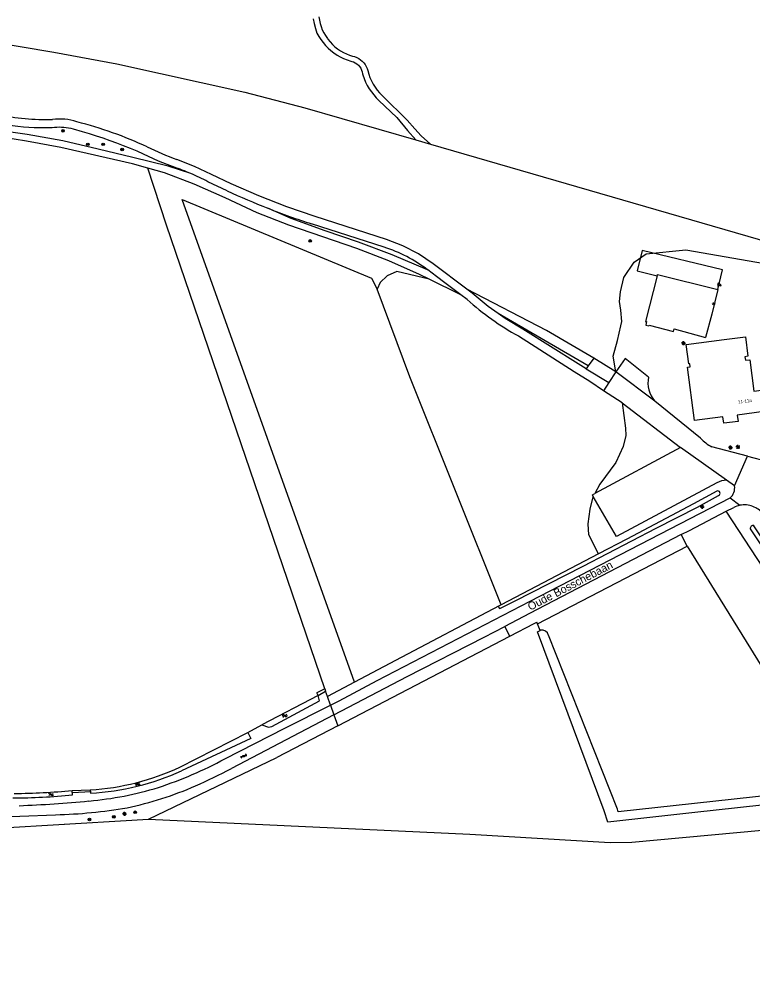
# Model space of a CAD drawing. Extents: x 137000 to 140001, y 403500 to 406000.
# Drawn here: x 138245 to 138474.3, y 405497.8 to 405796.6 of the extents above; entities that cross this region are included whole.
import ezdxf

# ---------------------------------------------------------------- set-up
doc = ezdxf.new("R2010")
doc.units = 0
for name, color, linetype in [('gg-afsc-draadraster', 7, 'Continuous'), ('gg-afsc-erfafscheiding', 7, 'Continuous'), ('gg-afsc-lijn draadraster', 7, 'Continuous'), ('gg-anno-huisnummerreeks BGT', 7, 'Continuous'), ('gg-anno-openbare ruimte label', 7, 'Continuous'), ('gg-bbg-bijgebouw', 7, 'Continuous'), ('gg-bbg-hoofdgebouw', 7, 'Continuous'), ('gg-bbg-luifel en loopbrug', 7, 'Continuous'), ('gg-knt-bronhoudergrens', 7, 'Continuous'), ('gg-knt-onverhard', 7, 'Continuous'), ('gg-knt-verharding', 7, 'Continuous'), ('gg-knt-verharding nz', 7, 'Continuous'), ('gg-kntw-bovenkant insteek waterloop', 7, 'Continuous'), ('gg-kwrk-duiker nz buis', 7, 'Continuous'), ('gt-grn-groengrens', 7, 'Continuous'), ('gt-grn-groengrens NZ', 7, 'Continuous'), ('gt-grn-weggrens', 7, 'Continuous'), ('gt-symb-boom', 7, 'Continuous'), ('gt-symb-camera', 7, 'Continuous'), ('gt-symb-gesloten verharding', 7, 'Continuous'), ('gt-symb-lichtmast', 7, 'Continuous'), ('gt-symb-lichtpunt', 7, 'Continuous'), ('gt-symb-watersymbool', 7, 'Continuous'), ('gx-grn-maaiveld', 7, 'Continuous')]:
    doc.layers.add(name, color=color, linetype=linetype)

# ---------------------------------------------------------------- blocks, each defined once
blk = doc.blocks.new('gt0-BOOM')
at = {"layer": 'gt-symb-boom'}
for radius in [0.4, 0.2]:
    blk.add_circle((0, 0), radius, dxfattribs=at)
blk = doc.blocks.new('gt0-WA')
at = {"layer": 'gt-symb-watersymbool'}
for centre, start, end in [((-0.32, 0.02), 28.0725, 151.9275), ((0.43, 0.42), 208.0725, 331.9275), ((-0.32, -0.43), 28.0725, 151.9275), ((0.43, -0.03), 208.0725, 331.9275)]:
    blk.add_arc(centre, 0.425, start, end, dxfattribs=at)
blk = doc.blocks.new('gt0-GESVH1')
at = {"layer": 'gt-symb-gesloten verharding'}
for p, q in [((-0.99, -0.26), (0.01, 0.24)), ((0.01, -0.26), (-0.99, 0.24)), ((0.01, 0.24), (1.01, -0.26)), ((1.01, 0.24), (0.01, -0.26))]:
    blk.add_line(p, q, dxfattribs=at)
blk = doc.blocks.new('gt0-LMAST')
at = {"layer": 'gt-symb-lichtmast'}
for p, q in [((-0.18, 0.17), (-0.45, 0.44)), ((-0.01, 0.25), (-0.01, 0.62)), ((0.17, 0.17), (0.44, 0.44)), ((-0.26, 0), (-0.63, 0)), ((-0.18, -0.18), (-0.45, -0.45)), ((-0.01, -0.25), (-0.01, -0.63)), ((0.44, -0.45), (0.17, -0.18)), ((0.24, 0), (0.62, 0))]:
    blk.add_line(p, q, dxfattribs=at)
blk.add_circle((-0.01, 0), 0.25, dxfattribs=at)
blk = doc.blocks.new('gt0-LPUNT')
at = {"layer": 'gt-symb-lichtpunt'}
for p, q in [((0, 0), (-0.25, 0)), ((0, 0), (0.25, 0)), ((-0.18, -0.18), (-0.44, -0.44)), ((0, -0.25), (0, -0.62)), ((0.44, -0.44), (0.18, -0.18))]:
    blk.add_line(p, q, dxfattribs=at)
blk.add_arc((0, 0), 0.25, 180, 0, dxfattribs=at)
blk = doc.blocks.new('gt0-CAMERA')
at = {"layer": 'gt-symb-camera'}
for points in [[(0.07, 0.48), (0.75, 0.16), (0.92, 0.51), (-0.12, 1), (-0.28, 0.65), (-0.07, 0.55)], [(0.07, 0.48), (0.07, 0), (-0.07, 0), (-0.07, 0.55)]]:
    blk.add_lwpolyline(points, dxfattribs=at)

msp = doc.modelspace()

# ---------------------------------------------------------------- linework, layer by layer
at = {"layer": 'gg-afsc-draadraster'}
msp.add_lwpolyline([(138285.47, 405546.77), (138385.85, 405542.03), (138429.7, 405539.4), (138436.46, 405539.56), (138519.15, 405547.11), (138520.63, 405545.63), (138532.33, 405527.32), (138568.1, 405472.11), (138619.55, 405394.28), (138620.49, 405392.37), (138614.17, 405385.79)], dxfattribs=at)
at = {"layer": 'gg-afsc-erfafscheiding'}
msp.add_lwpolyline([(138431.55, 405686.42), (138430.73, 405691.32), (138432.04, 405696.3), (138433.12, 405700.81), (138433.36, 405702.15), (138433.12, 405705.77), (138432.66, 405708.47), (138432.93, 405711.45), (138433.97, 405715.93), (138437.22, 405720.74), (138440.96, 405723.28), (138453.34, 405724.56), (138477.96, 405720.34)], dxfattribs=at)
at = {"layer": 'gg-afsc-lijn draadraster'}
for points in [[(138226.23, 405542.25), (138232.8, 405543.63), (138285.47, 405546.77)], [(138285.47, 405546.77), (138385.85, 405542.03), (138429.7, 405539.4), (138436.46, 405539.56), (138519.15, 405547.11), (138520.63, 405545.63), (138532.33, 405527.32), (138568.1, 405472.11), (138619.55, 405394.28), (138620.49, 405392.37), (138614.17, 405385.79)]]:
    msp.add_lwpolyline(points, dxfattribs=at)
at = {"layer": 'gg-bbg-bijgebouw'}
for points in [[(138444.42, 405716.42), (138440.83, 405702.23), (138441.12, 405702.15), (138440.87, 405701.09), (138441.86, 405700.85), (138441.91, 405701.07), (138449.54, 405699.07), (138449.76, 405699.89), (138459.53, 405697.24)], [(138444.42, 405716.42), (138444.55, 405716.91), (138463.35, 405712.21)], [(138463.35, 405712.21), (138461.49, 405704.48), (138459.53, 405697.24)]]:
    msp.add_lwpolyline(points, dxfattribs=at)
at = {"layer": 'gg-bbg-hoofdgebouw'}
msp.add_lwpolyline([(138481.15, 405674.49), (138480.83, 405674.45), (138469.46, 405672.97), (138469.72, 405670.99), (138465.26, 405670.4), (138465, 405672.39), (138456.09, 405671.22), (138453.9, 405687.96), (138454.75, 405688.07), (138454.63, 405688.96), (138454.33, 405688.93), (138453.54, 405694.97), (138465.4, 405696.52), (138472.02, 405697.38), (138472.81, 405691.33), (138471.87, 405691.2), (138472.02, 405690.06), (138473.35, 405690.24), (138474.63, 405680.44), (138480.27, 405681.18)], dxfattribs=at)
at = {"layer": 'gg-bbg-luifel en loopbrug'}
msp.add_lwpolyline([(138463.35, 405712.21), (138464.81, 405718.28), (138439.72, 405724.32), (138438.13, 405718.01), (138444.42, 405716.42)], dxfattribs=at)
at = {"layer": 'gg-knt-bronhoudergrens'}
for p, q in [((138340.53, 405587.49), (138338.04, 405586.16)), ((138340.53, 405587.49), (138340.8, 405586.68)), ((138338.46, 405585.38), (138338.04, 405586.16)), ((138342.33, 405582.38), (138343.43, 405579.32))]:
    msp.add_line(p, q, dxfattribs=at)
msp.add_lwpolyline([(138395.02, 405613.38), (138362.62, 405596.32), (138349.88, 405589.57)], dxfattribs=at)
at = {"layer": 'gg-knt-onverhard'}
for p, q in [((138383.06, 405710.52), (138373.21, 405715.4)), ((138422.88, 405688.35), (138394.75, 405704.67)), ((138451.74, 405662.79), (138424.98, 405648.45)), ((138453.8, 405631.99), (138451.91, 405635.61)), ((138453.8, 405631.99), (138484.73, 405581.93))]:
    msp.add_line(p, q, dxfattribs=at)
for points in [[(138298.71, 405748.38), (138291.67, 405750.67), (138280.55, 405753.44), (138269.75, 405756.04), (138258.71, 405758.6), (138247.55, 405760.57), (138235.93, 405762.25), (138224.91, 405763.99), (138214.16, 405765.74), (138203.06, 405767.46), (138191.74, 405768.79), (138180.55, 405769.9), (138169.49, 405770.78), (138158.07, 405771.24), (138146.37, 405771.82), (138123.29, 405772.35), (138112.32, 405772.64), (138100.04, 405772.6), (138088.68, 405772.36), (138077.76, 405772.23), (138066.69, 405771.54)], [(138285.29, 405750.05), (138280.52, 405751.41), (138258.08, 405756.52), (138247.37, 405758.48), (138235.71, 405760.38), (138224.67, 405762.12), (138213.74, 405763.92), (138202.85, 405765.65), (138191.37, 405767.11), (138180.28, 405768.09), (138169.32, 405769.1), (138157.83, 405769.33), (138146.06, 405769.86), (138134.82, 405769.79), (138123.36, 405769.77), (138111.63, 405769.44), (138100.16, 405769.1), (138088.48, 405769.03), (138077.67, 405770.26), (138067.55, 405769.1)], [(138373.21, 405715.4), (138370.2, 405716.9), (138360.59, 405721.11), (138350.54, 405724.95), (138329.28, 405732.26), (138319.44, 405736.14), (138309.42, 405740.82), (138299.79, 405745.14), (138290.43, 405748.59), (138285.29, 405750.05)], [(138372.66, 405718.38), (138361.6, 405723.06), (138351.07, 405726.97), (138340.68, 405730.55), (138330.07, 405734.34), (138322.78, 405737.57)], [(138424.64, 405690.75), (138409.87, 405699.34), (138384.91, 405712.31)], [(138463.12, 405651.8), (138431.69, 405635.06), (138424.47, 405647.49)], [(138424.47, 405647.49), (138424.17, 405648.01), (138424.98, 405648.45)]]:
    msp.add_lwpolyline(points, dxfattribs=at)
msp.add_arc((138466.38, 405645.66), 6.95, 92.2736, 117.957, dxfattribs=at)
at = {"layer": 'gg-knt-verharding'}
for p, q in [((138310.05, 405743.04), (138304.03, 405745.85)), ((138359.08, 405725.41), (138336.45, 405732.69)), ((138378.1, 405714.26), (138375.48, 405716.25)), ((138383.06, 405710.52), (138378.1, 405714.26)), ((138385.04, 405709.03), (138383.06, 405710.52)), ((138424.64, 405690.75), (138422.88, 405688.35)), ((138431.55, 405686.42), (138424.64, 405690.75)), ((138422.88, 405688.35), (138422.19, 405687.41)), ((138429.28, 405683.09), (138427.68, 405680.57)), ((138433.49, 405676.77), (138427.68, 405680.57)), ((138433.49, 405676.77), (138451.74, 405662.79)), ((138457.93, 405665.7), (138443.72, 405677.35)), ((138472.67, 405660.08), (138461.51, 405663.02)), ((138468.59, 405650.88), (138472.67, 405660.08)), ((138472.67, 405660.08), (138478.98, 405658.41)), ((138468.59, 405650.88), (138466.11, 405652.61)), ((138467.21, 405647.11), (138470.24, 405644.78)), ((138465.96, 405642.9), (138468.35, 405644.14)), ((138343.43, 405579.32), (138311.37, 405562.56))]:
    msp.add_line(p, q, dxfattribs=at)
for points in [[(138251.48, 405762.75), (138253.42, 405762.74), (138255.35, 405762.79), (138256.08, 405762.88), (138256.81, 405762.93), (138257.54, 405762.95), (138258.28, 405762.94), (138259.01, 405762.89), (138259.74, 405762.81), (138260.47, 405762.7), (138261.18, 405762.56), (138261.9, 405762.38), (138264.78, 405761.56), (138266.94, 405760.92), (138269.1, 405760.24), (138271.24, 405759.52), (138273.37, 405758.78), (138275.49, 405758), (138277.6, 405757.18), (138279.7, 405756.34), (138281.78, 405755.46), (138283.84, 405754.54), (138288.53, 405752.36), (138293.34, 405750.47)], [(138384.91, 405712.31), (138374.46, 405720.21), (138369.88, 405723.28), (138364.99, 405725.83), (138359.85, 405727.8), (138337.54, 405734.99), (138328.67, 405738.05), (138319.94, 405741.47), (138311.35, 405745.24), (138305.13, 405748.13), (138299.82, 405750.66), (138294.32, 405752.78)], [(138375.48, 405716.25), (138372.74, 405718.32), (138372.66, 405718.38)], [(138394.75, 405704.67), (138391.59, 405706.91), (138386.58, 405711.05), (138384.91, 405712.31)], [(138422.19, 405687.41), (138419.72, 405688.92), (138402.46, 405699.8), (138396.89, 405703.15), (138394.75, 405704.67)], [(138427.68, 405680.57), (138423.35, 405683.4), (138418.44, 405686.51), (138401.09, 405697.66)], [(138441.75, 405684.83), (138434.44, 405690.66), (138431.55, 405686.42)], [(138342.33, 405582.38), (138345.01, 405583.74), (138356.95, 405590.01), (138404.74, 405614.79), (138467.21, 405647.11)], [(138498.37, 405594.64), (138496.98, 405595.61), (138465.96, 405642.9)], [(138451.91, 405635.61), (138404.52, 405610.95), (138396.84, 405606.96)], [(138343.43, 405579.32), (138366.35, 405591.26), (138390.38, 405603.6), (138396.84, 405606.96)], [(138309.34, 405565.56), (138328.05, 405575.12), (138342.33, 405582.38)], [(138225.99, 405546.93), (138245.3, 405547.66), (138256.45, 405548.11)]]:
    msp.add_lwpolyline(points, dxfattribs=at)
for centre, radius, start, end in [((138253.63, 405838.54), 73.28, 258.011, 271.4201), ((138252.79, 405832.12), 69.38, 257.6621, 268.9163), ((138257.74, 405748.62), 16.81, 71.4381, 97.8284), ((138231.7, 405641.76), 126.75, 65.1062, 75.6635), ((138329.69, 405848.44), 101.99, 244.048, 249.7116), ((138267.86, 405676.83), 77.92, 66.678, 70.9157), ((138267.87, 405676.81), 77.93, 62.359, 66.6934), ((138405.93, 405948.72), 226.93, 245.007, 248.5057), ((138405.87, 405948.59), 226.79, 248.5079, 252.1748), ((138345.01, 405681.62), 46, 53.048, 72.1792), ((138444.46, 405775.97), 89.51, 228.4054, 241.0211), ((138450.11, 405683.03), 8.55, 167.8577, 221.677), ((138470.48, 405678.74), 18.1, 226.106, 240.2977), ((138464.69, 405650.17), 3.97, 309.4755, 10.2582), ((138471.68, 405637.35), 7.56, 100.9801, 116.1262), ((138471.67, 405637.38), 7.53, 69.2765, 100.9229), ((138471.67, 405637.38), 7.53, 40.0811, 69.2719), ((138247.27, 405681.29), 131.32, 288.3231, 298.2091), ((138227.91, 405720.03), 178.22, 293.9286, 297.9223), ((138255.41, 405660.38), 112.54, 281.9724, 293.45), ((138257.64, 405657.82), 105.82, 275.0083, 286.9877), ((138227.15, 405980.72), 430.15, 272.3841, 275.299), ((138253.01, 405699.02), 150.94, 271.3066, 279.8215)]:
    msp.add_arc(centre, radius, start, end, dxfattribs=at)
at = {"layer": 'gg-knt-verharding nz'}
for p, q in [((138422.19, 405687.41), (138429.28, 405683.09)), ((138443.72, 405677.35), (138431.55, 405686.42))]:
    msp.add_line(p, q, dxfattribs=at)
at = {"layer": 'gg-kntw-bovenkant insteek waterloop'}
for p, q in [((138426.09, 405629.57), (138395.64, 405613.7)), ((138395.64, 405613.7), (138395.02, 405613.38)), ((138338.46, 405585.38), (138320.9, 405576.2)), ((138295.31, 405562.98), (138316.54, 405573.76)), ((138261.73, 405554.31), (138261.63, 405555.69)), ((138267.27, 405555.87), (138267.35, 405554.85))]:
    msp.add_line(p, q, dxfattribs=at)
for points in [[(138395.02, 405613.38), (138394.83, 405613.15), (138395.1, 405612.61), (138395.24, 405612.56), (138399.84, 405614.86), (138421.35, 405625.81), (138444.08, 405637.63), (138457.05, 405644.17), (138463.64, 405647.83)], [(138463.07, 405649.22), (138455.76, 405645.2), (138434.94, 405634.18), (138426.09, 405629.57)], [(138501.09, 405596.29), (138500.67, 405596.36), (138500.4, 405596.63), (138495.05, 405604.87), (138485.03, 405620.21), (138473.59, 405637.42), (138473.57, 405637.78), (138473.94, 405638.36), (138474.34, 405638.54)], [(138501.09, 405596.29), (138501.43, 405596.53), (138501.65, 405597.18), (138501.53, 405597.71), (138490.96, 405613.85), (138474.68, 405638.39), (138474.34, 405638.54)], [(138320.9, 405576.2), (138322.93, 405575.47), (138324.02, 405575.69), (138338.93, 405583.74), (138338.46, 405585.38)], [(138316.54, 405573.76), (138317.47, 405571.94), (138295.81, 405561.84)]]:
    msp.add_lwpolyline(points, dxfattribs=at)
for centre, radius, start, end in [((138463.32, 405648.51), 0.753, 294.7618, 109.9861), ((138262.34, 405634.2), 78.48, 273.6022, 294.8459), ((138263.43, 405632.32), 77.56, 272.8996, 294.6788), ((138241.88, 405761.19), 207.83, 270.3196, 275.481), ((138242.11, 405761.38), 206.62, 270.3927, 275.4202)]:
    msp.add_arc(centre, radius, start, end, dxfattribs=at)
at = {"layer": 'gg-kwrk-duiker nz buis'}
msp.add_line((138261.58, 405555.07), (138267.58, 405555.36), dxfattribs=at)
at = {"layer": 'gt-grn-groengrens'}
for p, q in [((138407.07, 405607.75), (138406.85, 405608.3)), ((138407.88, 405605.69), (138407.07, 405607.75)), ((138407.88, 405605.69), (138408.01, 405605.75)), ((138344.68, 405575.88), (138398.4, 405603.89)), ((138338.46, 405585.38), (138340.8, 405586.68)), ((138341.36, 405585.05), (138340.8, 405586.68)), ((138316.54, 405573.76), (138320.9, 405576.2)), ((138344.68, 405575.88), (138325.57, 405566.01)), ((138285.47, 405546.77), (138325.57, 405566.01)), ((138261.63, 405555.69), (138267.27, 405555.87))]:
    msp.add_line(p, q, dxfattribs=at)
for points in [[(138224.22, 405791.62), (138255.86, 405786.31), (138275.53, 405782.73), (138315.61, 405773.79), (138334.36, 405768.96), (138368.98, 405758.93)], [(138373.64, 405757.58), (138476.03, 405727.91), (138477.92, 405727.28)], [(138340.53, 405587.49), (138291.07, 405732.26), (138285.29, 405750.05)], [(138349.88, 405589.57), (138296.04, 405740.29), (138355.2, 405715.72), (138356.88, 405712.27)], [(138373.21, 405715.4), (138363.03, 405717.77), (138360.05, 405716.43), (138357.89, 405714.36), (138356.88, 405712.27)], [(138395.64, 405613.7), (138367.14, 405684.9), (138356.88, 405712.27)], [(138433.49, 405676.77), (138434.52, 405668.85), (138434.59, 405666.53), (138433.84, 405663.12), (138431.47, 405658.13), (138426.53, 405651.34), (138424.98, 405648.45)], [(138398.4, 405603.89), (138405.94, 405607.82), (138406.85, 405608.3)], [(138429.04, 405545.84), (138427.87, 405549.38), (138407.02, 405605.29), (138407.88, 405605.69)], [(138524.83, 405559.27), (138511.38, 405557.67), (138456.11, 405551.62), (138432.28, 405548.99), (138432.01, 405549.85), (138410.47, 405604.16)], [(138526.55, 405556.66), (138511.42, 405554.88), (138456.15, 405548.84), (138429.04, 405545.84)], [(138226.23, 405542.25), (138232.8, 405543.63), (138285.47, 405546.77)]]:
    msp.add_lwpolyline(points, dxfattribs=at)
msp.add_arc((138408.41, 405603.66), 2.12, 13.3934, 101.0024, dxfattribs=at)
at = {"layer": 'gt-grn-groengrens NZ'}
for p, q in [((138407.07, 405607.75), (138453.8, 405631.99)), ((138349.88, 405589.57), (138341.36, 405585.05)), ((138342.33, 405582.38), (138341.36, 405585.05)), ((138343.43, 405579.32), (138344.68, 405575.88))]:
    msp.add_line(p, q, dxfattribs=at)
msp.add_lwpolyline([(138426.09, 405629.57), (138423.06, 405635.54), (138422.86, 405638.97), (138423.44, 405643.52), (138424.41, 405647.38), (138424.47, 405647.49)], dxfattribs=at)
at = {"layer": 'gt-grn-weggrens'}
for p, q in [((138466.11, 405652.61), (138451.74, 405662.79)), ((138454.49, 405636.95), (138465.96, 405642.9)), ((138451.91, 405635.61), (138454.49, 405636.95)), ((138398.4, 405603.89), (138396.84, 405606.96))]:
    msp.add_line(p, q, dxfattribs=at)
at = {"layer": 'gx-grn-maaiveld'}
for p, q in [((138368.98, 405758.93), (138373.64, 405757.58)), ((138431.55, 405686.42), (138429.28, 405683.09))]:
    msp.add_line(p, q, dxfattribs=at)
for points in [[(138336.97, 405796.75), (138337.27, 405795.24), (138337.65, 405793.74), (138338.11, 405792.26), (138338.68, 405791.24), (138339.32, 405790.25), (138340.02, 405789.31), (138340.78, 405788.42), (138341.61, 405787.58), (138342.49, 405786.8), (138343.41, 405786.09), (138344.39, 405785.43), (138345.41, 405784.85), (138346.46, 405784.34), (138347.55, 405783.9), (138348.67, 405783.53), (138348.97, 405783.46), (138349.55, 405783.27), (138350.09, 405783), (138350.6, 405782.66), (138351.05, 405782.26), (138351.46, 405781.8), (138351.79, 405781.3), (138352.06, 405780.75), (138352.25, 405780.17), (138352.37, 405779.58), (138352.48, 405779.21), (138352.86, 405778.08), (138353.32, 405776.98), (138353.85, 405775.92), (138354.45, 405774.89), (138355.11, 405773.91), (138355.85, 405772.97), (138356.64, 405772.09), (138357.49, 405771.26), (138363.03, 405765.95), (138366.43, 405761.85), (138368.98, 405758.93)], [(138338.71, 405797.37), (138338.86, 405796.33), (138339.09, 405795.31), (138339.4, 405794.31), (138339.78, 405793.33), (138340.24, 405792.39), (138340.77, 405791.48), (138341.37, 405790.62), (138341.54, 405790.39), (138342.21, 405789.55), (138342.93, 405788.77), (138343.72, 405788.04), (138344.55, 405787.38), (138345.43, 405786.77), (138346.36, 405786.24), (138347.32, 405785.77), (138348.32, 405785.38), (138349.21, 405785.1), (138349.89, 405784.93), (138350.55, 405784.67), (138351.17, 405784.35), (138351.75, 405783.96), (138352.29, 405783.5), (138352.77, 405782.99), (138353.18, 405782.42), (138353.53, 405781.81), (138353.81, 405781.17), (138353.99, 405780.57), (138354.3, 405779.48), (138354.69, 405778.4), (138355.15, 405777.36), (138355.69, 405776.35), (138356.29, 405775.39), (138356.96, 405774.46), (138357.69, 405773.59), (138358.49, 405772.77), (138358.71, 405772.56), (138366.3, 405765.04), (138368.68, 405762.38), (138370.71, 405760.24), (138373.64, 405757.58)]]:
    msp.add_lwpolyline(points, dxfattribs=at)

# ---------------------------------------------------------------- block references
at = {"layer": 'gt-symb-boom'}
for p in [(138258.76, 405761.77), (138266.5, 405757.54), (138271.3, 405757.54), (138277.24, 405755.9), (138336, 405727.36), (138281.3, 405548.89), (138267, 405546.63), (138274.62, 405547.48)]:
    msp.add_blockref('gt0-BOOM', p, dxfattribs=at)
at = {"layer": 'gt-symb-camera'}
msp.add_blockref('gt0-CAMERA', (138463.56, 405713.15), dxfattribs=at)
at = {"layer": 'gt-symb-gesloten verharding', "rotation": 27.00065470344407}
msp.add_blockref('gt0-GESVH1', (138315.2, 405566.44), dxfattribs=at)
at = {"layer": 'gt-symb-lichtmast'}
for p in [(138452.66, 405695.38), (138467.37, 405662.8), (138469.69, 405663.01), (138458.48, 405644.33), (138277.99, 405548.4)]:
    msp.add_blockref('gt0-LMAST', p, dxfattribs=at)
at = {"layer": 'gt-symb-lichtpunt'}
msp.add_blockref('gt0-LPUNT', (138462.1, 405707.93), dxfattribs=at)
at = {"layer": 'gt-symb-watersymbool'}
for p, rotation in [((138328.05, 405579.03), 27.00065470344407), ((138282.05, 405557.61), 27.00065470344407), ((138254.95, 405554.44), 11.00666417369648)]:
    msp.add_blockref('gt0-WA', p, dxfattribs=dict(at, rotation=rotation))

# ---------------------------------------------------------------- texts
at = {"layer": 'gg-anno-huisnummerreeks BGT'}
msp.add_text('11-11a', height=1, rotation=7.4, dxfattribs=at).set_placement((138469.78, 405676.54))
at = {"layer": 'gg-anno-openbare ruimte label'}
msp.add_text('Oude Bosschebaan', height=2.5, rotation=27.5, dxfattribs=at).set_placement((138404.78, 405611.8))

doc.saveas('drawing.dxf')
